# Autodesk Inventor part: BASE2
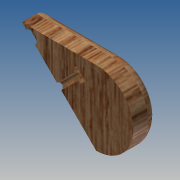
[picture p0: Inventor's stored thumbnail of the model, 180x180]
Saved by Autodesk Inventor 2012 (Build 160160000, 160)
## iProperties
Created: 2011-01
Part Number: BASE2
Document SubType Name: Modeling
Designer: Microsoft
Density: 1 g/cm^3
Material: Default
Author: Microsoft
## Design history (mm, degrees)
sketch "Sketch1"
  geometry: L1 (9.525, 0)-(9.525, 19.05); L2 (-9.525, 19.05)-(-9.525, 0); L3 (-9.525, 19.05)-(9.525, 0); A1 r 9.525 centre (0, 0) between (-9.525, 0) and (9.525, 0); A2 r 9.525 centre (0, 19.05) between (9.525, 19.05) and (-9.525, 19.05); 1 further point
  constraints: 6 end point, 4 point on circle, 3 tangent, 2 centre point, 1 coincident, 1 vertical alignment
  dimensions: "d3" = 9.525 radius of A2; "d4" = 9.525 radius of A1; "d5" = 19.05 distance of L1.start L1.end; "d6" = 19.05 distance of point (0, 0) A2.centre
extrude "Extrusion1" new body sketch "Sketch1" distance "d7" = 12.7; taper "d8" = 0 deg
sketch "Sketch2"
  geometry: L1 (13.47, 0)-(13.47, 12.7) reference; L2 (0, 0)-(26.941, 0) reference; C1 r 0.794 at (13.47, 6.35); 1 further point
  constraints: 1 centre point, 1 midpoint
  dimensions: "d31" = 1.5875 diameter of C1; "d32" = 6.35 distance from line of L2 C1.centre
extrude "Extrusion2" cut sketch "Sketch2" distance "d10" = 6.35; taper "d11" = 0 deg
sketch "Sketch3"
  geometry: C1 r 1.587 at (0, -3.175); C2 r 0.794 at (0, -3.175) reference; 1 further point
  constraints: 1 centre point, 1 concentric
  dimensions: "d12" = 3.175 diameter of C1
extrude "Extrusion3" cut sketch "Sketch3" distance "d13" = 1.5875; taper "d14" = 0 deg
workplane "Work Plane1"
sketch "Sketch5"
  geometry: L1 (-9.525, 19.05)-(-8.622, 19.953); L2 (9.525, 0)-(-9.525, 19.05) reference; C1 r 0.794 at (-7.28, 16.805); 1 further point
  constraints: 2 end point, 1 centre point, 1 perpendicular, 1 point on line
  dimensions: "d21" = 1.5875 diameter of C1; "d22" = 3.175 distance from line of L1 C1.centre
extrude "Extrusion4" cut sketch "Sketch5" distance "d23" = 3.175; taper "d24" = 0 deg
sketch "Sketch6"
  geometry: C1 r 1.588 at (-7.28, -16.805); A1 r 0.794 centre (-7.28, -16.805) between (-6.719, -16.244) and (-7.841, -17.366) reference; 1 further point
  constraints: 1 centre point, 1 coincident
  dimensions: "d25" = 3.175 diameter of C1
extrude "Extrusion5" cut sketch "Sketch6" distance "d26" = 1.5875; taper "d27" = 0 deg
fillet "Fillet1" dims "d30" = 2.54
sketch "Sketch8"
  geometry: L1 (-9.525, 19.05)-(9.525, 0) reference; L2 (-9.525, 0)-(-9.525, 19.05) reference; A1 r 9.525 centre (0, 0) between (-9.525, 0) and (9.525, 0) reference
extrude "Extrusion7" cut sketch "Sketch8" distance "d33" = 3.175; taper "d34" = 0 deg
sketch "Sketch9"
  geometry: L1 (7.841, -17.366)-(6.719, -16.244) reference; C1 r 1.588 at (7.28, -16.805); A1 r 0.794 centre (7.28, -16.805) between (6.719, -16.244) and (7.841, -17.366) reference; 1 further point
  constraints: 1 centre point, 1 coincident
  dimensions: "d37" = 3.175 diameter of C1
extrude "Extrusion8" cut sketch "Sketch9" distance "d35" = 0.79375; taper "d36" = 0 deg
sketch "Sketch10"
  geometry: L1 (-6.719, 16.244)-(9.525, 0) reference; L2 (-9.525, 19.05)-(-7.841, 17.366) reference; L3 (-9.525, 0)-(-9.525, 19.05) reference; A1 r 0.794 centre (-7.28, 16.805) between (-7.841, 17.366) and (-6.719, 16.244) reference; A2 r 9.525 centre (0, 0) between (-9.525, 0) and (9.525, 0) reference
extrude "Extrusion9" cut sketch "Sketch10" distance "d38" = 3.175; taper "d39" = 0 deg
mirror "Mirror1"
body "Solid1"
other parameters: "d17" = -6.35
